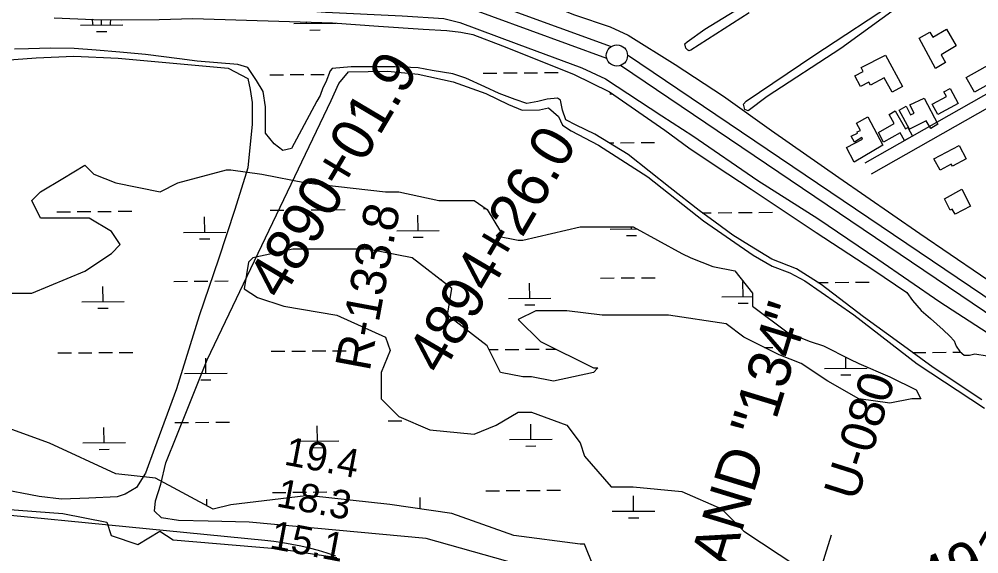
# Model space of a CAD drawing. Extents: x 3540316 to 3578335, y 553172 to 578787.
# Drawn here: x 3547262 to 3549520, y 567214 to 568472 of the extents above; entities that cross this region are included whole.
import ezdxf

# ---------------------------------------------------------------- set-up
doc = ezdxf.new("R2010")
doc.units = 0
for name, color, linetype in [('V-BLDG-OTLN', 7, 'Continuous'), ('V-CHAN-NAID', 7, 'Continuous'), ('V-LEVE-TOET', 7, 'Continuous'), ('V-RIVR-RANG', 7, 'Continuous'), ('V-RIVR-RANG-IDEN', 7, 'Continuous'), ('V-ROAD-CNTR', 7, 'Continuous'), ('V-SITE-VEGE', 7, 'Continuous'), ('V-SURV-IDEN', 7, 'Continuous'), ('V-SURV-LINE', 7, 'Continuous'), ('V-TOPO-MINR', 7, 'Continuous'), ('V-WETL-SWMP', 7, 'Continuous')]:
    doc.layers.add(name, color=color, linetype=linetype)

msp = doc.modelspace()

# ---------------------------------------------------------------- linework, layer by layer
at = {"layer": 'V-BLDG-OTLN'}
for points in [[(3549404.7, 568441.6), (3549411.5, 568430), (3549443.8, 568448.8), (3549467, 568409.1), (3549431, 568388.1), (3549441.6, 568370), (3549418.2, 568356.3), (3549379.8, 568427.7)], [(3549300.2, 568387.6), (3549340.4, 568313.5), (3549315.9, 568300.2), (3549297.5, 568334.2), (3549265, 568316.6), (3549260.9, 568324.2), (3549242, 568314), (3549228.6, 568338.9), (3549247.8, 568349.2), (3549242.9, 568358.2)], [(3549554.8, 568370.9), (3549574.4, 568336.3), (3549510, 568300), (3549490.2, 568335)], [(3549410.6, 568272.1), (3549411.9, 568273), (3549443.7, 568290), (3549437.7, 568301.3), (3549452.5, 568309.2), (3549471.6, 568273.4), (3549423.5, 568247.8)], [(3549357.9, 568270.4), (3549391.5, 568286.6), (3549423.9, 568225.2), (3549407, 568214.8), (3549396, 568233.2), (3549357.2, 568213.5), (3549332.3, 568258.1), (3549349.4, 568267.2), (3549359.5, 568246.8), (3549368.2, 568251)], [(3549283.8, 568205.2), (3549321, 568226.6), (3549308.9, 568247.8), (3549323.4, 568256.1), (3549347.5, 568214.1), (3549352.6, 568217), (3549364.1, 568197.1), (3549345.3, 568186.3), (3549335, 568204.3), (3549295.9, 568182.8)], [(3549259.2, 568242), (3549294.4, 568175.6), (3549227.1, 568135.8), (3549209, 568170.1), (3549246.5, 568189.8), (3549244.6, 568193.4), (3549227.8, 568182.7), (3549220, 568196.6), (3549234.9, 568203.8), (3549233.6, 568206.7), (3549241.4, 568210.1), (3549232, 568227.2)], [(3549429.4, 568116.9), (3549414.3, 568143.4), (3549473.4, 568175.1), (3549490.2, 568143.7), (3549457.7, 568126.3), (3549455.3, 568130.8)], [(3549479.9, 568071.7), (3549500.5, 568032), (3549464, 568013), (3549457.6, 568025.3), (3549452.8, 568022.8), (3549439.1, 568049.1)]]:
    msp.add_lwpolyline(points, close=True, dxfattribs=at)
at = {"layer": 'V-LEVE-TOET'}
for points in [[(3547740.4, 568609.2), (3547885.3, 568608.2), (3548075.1, 568600.8), (3548243, 568593), (3548285, 568586), (3548432, 568537), (3548569, 568482.3), (3548652.6, 568454.3), (3548695, 568434.6), (3548805.3, 568365.5), (3548919, 568290.6), (3549032.2, 568209.9), (3549190.9, 568099.3), (3549381.1, 567967.7), (3549524, 567870.8), (3549685.8, 567762.2), (3549864, 567644.5), (3550011.8, 567540.4), (3550143.1, 567453.9), (3550243.6, 567377.8)], [(3547729.2, 568503.5), (3547828.5, 568500.7), (3547982.8, 568488.8), (3548163.5, 568480.2), (3548261.1, 568473.6), (3548299, 568464.6), (3548431.9, 568415.2), (3548585.9, 568358), (3548641.4, 568332.1), (3548774, 568244.8), (3548846.9, 568197.5), (3549000.4, 568092.2), (3549141.2, 568002.9), (3549282.4, 567907.4), (3549428.5, 567807), (3549582.3, 567707.3), (3549721.7, 567617.3), (3549855.6, 567525.7), (3550026.9, 567407.2), (3550093.6, 567363.1)]]:
    msp.add_lwpolyline(points, dxfattribs=at)
at = {"layer": 'V-RIVR-RANG'}
msp.add_line((3549172.9, 567257.8), (3548625.9, 565522), dxfattribs=at)
at = {"layer": 'V-ROAD-CNTR'}
for points in [[(3549252.6, 568134.4), (3549839.8, 568467.5)], [(3549267.4, 568108.3), (3549854.6, 568441.4)]]:
    msp.add_lwpolyline(points, dxfattribs=at)
at = {"layer": 'V-SITE-VEGE'}
for p, q in [((3547229, 568376), (3547302.2, 568381.2)), ((3547302.2, 568381.2), (3547390.7, 568384.9)), ((3547390.7, 568384.9), (3547495.6, 568380.3)), ((3547495.6, 568380.3), (3547753.8, 568357)), ((3547753.8, 568357), (3547800.6, 568332.6)), ((3547800.6, 568332.6), (3547805.7, 568306.9)), ((3547805.7, 568306.9), (3547810.8, 568276.1)), ((3547810.8, 568276.1), (3547810.8, 568224.7)), ((3547810.8, 568224.7), (3547800.5, 568121.9)), ((3547800.5, 568121.9), (3547769.7, 568024.3)), ((3547769.7, 568024.3), (3547731.7, 567907.5)), ((3547731.7, 567907.5), (3547685.8, 567773.9)), ((3547685.8, 567773.9), (3547632.9, 567602)), ((3547632.9, 567602), (3547581.1, 567461.5)), ((3547581.1, 567461.5), (3547559.2, 567403.5)), ((3547559.2, 567403.5), (3547538.3, 567370.2)), ((3547309.7, 567348.9), (3547197.9, 567369.6)), ((3547511.7, 567354.5), (3547492.9, 567348.1)), ((3547538.3, 567370.2), (3547511.7, 567354.5)), ((3547361.7, 567342.6), (3547309.7, 567348.9)), ((3547426.5, 567344.9), (3547361.7, 567342.6)), ((3547492.9, 567348.1), (3547426.5, 567344.9))]:
    msp.add_line(p, q, dxfattribs=at)
for points in [[(3548979.5, 568487.3), (3548842.3, 568399.3), (3548837.8, 568398), (3548835.2, 568399.3), (3548830.6, 568403.8), (3548828.7, 568414.2), (3548833.9, 568418.7), (3548875.3, 568448.5), (3549002.8, 568526.8)], [(3549341.3, 568509.4), (3549195.7, 568403.2), (3549022.2, 568289.9), (3548977.6, 568256.3), (3548969.8, 568259.5), (3548966.6, 568271.8), (3548973, 568278.9), (3549131.6, 568387), (3549334.8, 568521)], [(3549150, 566988.1), (3548219.5, 567249.8), (3547803.5, 567288.5), (3547707.2, 567290.4), (3547637.5, 567292), (3547597.3, 567298.2), (3547580.7, 567314.1), (3547582.9, 567338.6), (3547596, 567377.8), (3547607.1, 567427.9), (3547658.8, 567556.6), (3547704.6, 567670.5), (3547996.2, 568280.9), (3548014.4, 568320.5), (3548037.4, 568348.5), (3548129.6, 568350.1), (3548201.2, 568342.7), (3548283.5, 568324.6), (3548360.1, 568297.5), (3548413.6, 568271.1), (3548445.7, 568258), (3548486.1, 568258.8), (3548507.5, 568263.7), (3548531.4, 568243.2), (3548540.4, 568222.6), (3548561, 568209.4), (3548625.2, 568175.7), (3548741.3, 568100.8), (3548872.2, 567997.9), (3548989.1, 567916.4), (3549033.6, 567890.9), (3549075.6, 567875.3), (3549111, 567856.3), (3549226.2, 567776.5), (3549375.3, 567661.3), (3549533.3, 567556.7)]]:
    msp.add_lwpolyline(points, dxfattribs=at)
at = {"layer": 'V-SURV-LINE'}
for points in [[(3548294.1, 568539.3), (3548654.9, 568407.6)], [(3548644.6, 568379.4), (3548283.8, 568511.1)], [(3548693.5, 568387.9), (3550036.7, 567480.5)], [(3550019.9, 567455.6), (3548676.7, 568363.1)]]:
    msp.add_lwpolyline(points, dxfattribs=at)
msp.add_circle((3548668.6, 568386.7), 25, dxfattribs=at)
at = {"layer": 'V-TOPO-MINR'}
msp.add_lwpolyline([(3548007.1, 567208.3), (3547986.8, 567215.2), (3547966.4, 567221.5), (3547945.6, 567227), (3547924.7, 567231.9), (3547903.7, 567235.9), (3547882.5, 567239.5), (3547861.3, 567242.5), (3547840, 567244.9), (3546866.5, 567340.8), (3546827.9, 567343.8), (3546789.2, 567345.7), (3546750.5, 567345.8), (3546711.8, 567344.9), (3546673.1, 567342.9), (3546634.4, 567340.7), (3546607.3, 567338.8)], dxfattribs=at)
at = {"layer": 'V-WETL-SWMP'}
for p, q in [((3547406.3, 568457.9), (3547506.3, 568458.7)), ((3547456.3, 568458.3), (3547456.2, 568471.5)), ((3547908.2, 568461.8), (3548008.2, 568462.6)), ((3547958.2, 568462.2), (3547958.1, 568465)), ((3547444.4, 568442.8), (3547468.4, 568443)), ((3547946.3, 568446.6), (3547970.3, 568446.8)), ((3548354.1, 568345.1), (3548386.1, 568345.4)), ((3548402.1, 568345.5), (3548434.1, 568345.8)), ((3548450.1, 568345.9), (3548482.1, 568346.1)), ((3548498.1, 568346.3), (3548530.1, 568346.5)), ((3547852.2, 568341.3), (3547884.2, 568341.5)), ((3547900.2, 568341.6), (3547932.2, 568341.9)), ((3547948.2, 568342), (3547980.2, 568342.3)), ((3548651.8, 568296.7), (3548657, 568296.7)), ((3548650.2, 568181.2), (3548661.3, 568181.3)), ((3548677.3, 568181.5), (3548709.3, 568181.7)), ((3548725.3, 568181.8), (3548757.3, 568182.1)), ((3547365, 568097), (3547417, 568128.2)), ((3547417, 568128.2), (3547437.8, 568107.4)), ((3547312.9, 568065.9), (3547365, 568097)), ((3547437.8, 568107.4), (3547489.8, 568086.7)), ((3547635.5, 568086.7), (3547749.9, 568117.9)), ((3547749.9, 568117.9), (3547760.3, 568117.9)), ((3547760.3, 568117.9), (3547833.1, 568107.5)), ((3547833.1, 568107.5), (3547937.2, 568086.8)), ((3547489.8, 568086.7), (3547593.8, 568066)), ((3547593.8, 568066), (3547635.5, 568086.7)), ((3547937.2, 568086.8), (3548124.4, 568066.1)), ((3547292.1, 568045.2), (3547312.9, 568065.9)), ((3548124.4, 568066.1), (3548134.8, 568066.1)), ((3548134.8, 568066.1), (3548155.6, 568066.1)), ((3548155.6, 568066.1), (3548249.3, 568045.3)), ((3547312.9, 568003.7), (3547292.1, 568045.2)), ((3548249.3, 568045.3), (3548332.5, 568045.3)), ((3548332.5, 568045.3), (3548363.7, 568024.6)), ((3547351.2, 568018.8), (3547383.2, 568019)), ((3547399.2, 568019.2), (3547431.2, 568019.4)), ((3547447.2, 568019.5), (3547479.2, 568019.8)), ((3547495.2, 568019.9), (3547527.2, 568020.2)), ((3547698.9, 567970.8), (3547698.7, 568006.8)), ((3547853.1, 568022.7), (3547885.1, 568022.9)), ((3547901.1, 568023), (3547933.1, 568023.3)), ((3547949.1, 568023.4), (3547981.1, 568023.7)), ((3547997.1, 568023.8), (3548029.1, 568024)), ((3548200.8, 567974.7), (3548200.5, 568010.6)), ((3548355, 568026.5), (3548360.7, 568026.6)), ((3548363.7, 568024.6), (3548394.9, 567972.7)), ((3548869.3, 568016.4), (3548890.6, 568016.6)), ((3548906.6, 568016.7), (3548938.6, 568017)), ((3548954.6, 568017.1), (3548986.6, 568017.3)), ((3549002.6, 568017.5), (3549034.6, 568017.7)), ((3547375.3, 568003.7), (3547312.9, 568003.7)), ((3547427.4, 568003.7), (3547375.3, 568003.7)), ((3547479.4, 567972.6), (3547427.4, 568003.7)), ((3547500.2, 567941.5), (3547479.4, 567972.6)), ((3547648.9, 567970.4), (3547748.9, 567971.2)), ((3548150.8, 567974.3), (3548250.8, 567975.1)), ((3548394.9, 567972.7), (3548384.5, 567962.4)), ((3548384.5, 567962.4), (3548436.5, 567952)), ((3548446.9, 567952), (3548582.2, 567983.1)), ((3548582.2, 567983.1), (3548655, 567983.2)), ((3548652.7, 567978.2), (3548715.3, 567978.6)), ((3548655, 567983.2), (3548707, 567983.2)), ((3548690.8, 567963), (3548714.8, 567963.2)), ((3548702.7, 567978.5), (3548702.7, 567983.2)), ((3548707, 567983.2), (3548821.4, 567920.9)), ((3547479.4, 567920.7), (3547500.2, 567941.5)), ((3547687, 567955.3), (3547711, 567955.5)), ((3548188.9, 567959.2), (3548212.9, 567959.4)), ((3548436.5, 567952), (3548446.9, 567952)), ((3547416.9, 567879.2), (3547479.4, 567920.7)), ((3547905.9, 567931.2), (3547812.3, 567910.4)), ((3547999.6, 567931.2), (3547905.9, 567931.2)), ((3548082.8, 567931.2), (3547999.6, 567931.2)), ((3548186.8, 567910.5), (3548082.8, 567931.2)), ((3548821.4, 567920.9), (3548842.2, 567910.6)), ((3547801.9, 567900), (3547791.5, 567837.8)), ((3547812.3, 567910.4), (3547801.9, 567900)), ((3548280.4, 567837.9), (3548186.8, 567910.5)), ((3548842.2, 567910.6), (3548894.3, 567889.8)), ((3547292.1, 567827.3), (3547416.9, 567879.2)), ((3548894.3, 567889.8), (3548946.3, 567879.5)), ((3548946.3, 567879.5), (3548987.9, 567827.6)), ((3547626.4, 567855), (3547658.4, 567855.2)), ((3547674.4, 567855.4), (3547706.4, 567855.6)), ((3547722.4, 567855.7), (3547754.4, 567856)), ((3548252.1, 567859.8), (3548256.3, 567859.8)), ((3548463.5, 567815.1), (3548463.2, 567851)), ((3548630.2, 567862.7), (3548662.2, 567863)), ((3548678.2, 567863.1), (3548710.2, 567863.3)), ((3548726.2, 567863.5), (3548758.2, 567863.7)), ((3548965.4, 567818.9), (3548965.1, 567854.9)), ((3549141.5, 567852.4), (3549165.8, 567852.5)), ((3549181.8, 567852.7), (3549213.8, 567852.9)), ((3549229.8, 567853), (3549261.8, 567853.3)), ((3547156.8, 567827.3), (3547292.1, 567827.3)), ((3547459.7, 567807.3), (3547459.4, 567843.3)), ((3547791.5, 567837.8), (3547822.7, 567817)), ((3548270, 567775.6), (3548280.4, 567837.9)), ((3548987.9, 567827.6), (3548987.9, 567796.5)), ((3547409.7, 567806.9), (3547509.7, 567807.7)), ((3547822.7, 567817), (3547885.1, 567796.3)), ((3548413.5, 567814.7), (3548513.5, 567815.5)), ((3548915.4, 567818.6), (3548987.9, 567819.1)), ((3548953.5, 567803.4), (3548977.5, 567803.6)), ((3547447.8, 567791.8), (3547471.8, 567792)), ((3547885.1, 567796.3), (3548009.9, 567775.6)), ((3548478.1, 567786), (3548436.5, 567765.3)), ((3548451.6, 567799.6), (3548475.6, 567799.8)), ((3548550.9, 567786), (3548478.1, 567786)), ((3548634.1, 567775.7), (3548550.9, 567786)), ((3548987.9, 567796.5), (3549071.1, 567734.3)), ((3548009.9, 567775.6), (3548124.4, 567723.7)), ((3548363.6, 567703), (3548270, 567775.6)), ((3548436.5, 567765.3), (3548488.5, 567713.4)), ((3548769.4, 567775.7), (3548634.1, 567775.7)), ((3548790.2, 567775.7), (3548769.4, 567775.7)), ((3548925.4, 567755), (3548790.2, 567775.7)), ((3548967.1, 567723.9), (3548925.4, 567755)), ((3548124.4, 567723.7), (3548134.8, 567692.6)), ((3548488.5, 567713.4), (3548613.3, 567651.2)), ((3549050.3, 567682.4), (3548967.1, 567723.9)), ((3549071.1, 567734.3), (3549123.1, 567713.5)), ((3549123.1, 567713.5), (3549154.3, 567703.1)), ((3547855.6, 567690.5), (3547887.6, 567690.7)), ((3547903.6, 567690.8), (3547935.6, 567691.1)), ((3547951.6, 567691.2), (3547983.6, 567691.5)), ((3547999.6, 567691.6), (3548031.6, 567691.8)), ((3548134.8, 567692.6), (3548113.9, 567640.7)), ((3548394.8, 567640.8), (3548363.6, 567703)), ((3548367.9, 567694.4), (3548389.5, 567694.6)), ((3548405.5, 567694.7), (3548437.5, 567695)), ((3548453.5, 567695.1), (3548485.5, 567695.3)), ((3548501.5, 567695.5), (3548524.1, 567695.6)), ((3549016.1, 567699.4), (3549035.4, 567699.6)), ((3549154.3, 567703.1), (3549216.7, 567672)), ((3547353.7, 567686.6), (3547385.7, 567686.9)), ((3547401.7, 567687), (3547433.7, 567687.2)), ((3547449.7, 567687.3), (3547481.7, 567687.6)), ((3547497.7, 567687.7), (3547529.7, 567688)), ((3547701.4, 567638.6), (3547701.2, 567674.6)), ((3549102.3, 567661.6), (3549050.3, 567682.4)), ((3549207.1, 567650.2), (3549206.9, 567676.9)), ((3549216.7, 567672), (3549237.5, 567661.7)), ((3549364.2, 567687.6), (3549395, 567687.8)), ((3549411, 567687.9), (3549443, 567688.2)), ((3549459, 567688.3), (3549477.2, 567688.4)), ((3548613.3, 567651.2), (3548623.7, 567651.2)), ((3548623.7, 567651.2), (3548613.3, 567640.8)), ((3549164.7, 567620.2), (3549102.3, 567661.6)), ((3549157.1, 567649.8), (3549257.1, 567650.6)), ((3549237.5, 567661.7), (3549310.4, 567630.6)), ((3547651.4, 567638.2), (3547751.4, 567639)), ((3547689.6, 567623.1), (3547713.6, 567623.3)), ((3548113.9, 567640.7), (3548113.9, 567578.5)), ((3548446.9, 567630.4), (3548394.8, 567640.8)), ((3548467.7, 567630.4), (3548446.9, 567630.4)), ((3548519.7, 567620), (3548467.7, 567630.4)), ((3548613.3, 567640.8), (3548519.7, 567620)), ((3549195.2, 567634.7), (3549219.2, 567634.9)), ((3549310.4, 567630.6), (3549372.8, 567599.4)), ((3549237.5, 567578.7), (3549164.7, 567620.2)), ((3548113.9, 567578.5), (3548155.5, 567537)), ((3549310.3, 567568.3), (3549237.5, 567578.7)), ((3549362.4, 567578.7), (3549310.3, 567568.3)), ((3549383.2, 567578.7), (3549362.4, 567578.7)), ((3549372.8, 567599.4), (3549383.2, 567578.7)), ((3548155.5, 567537), (3548228.4, 567505.9)), ((3548384.4, 567516.3), (3548436.4, 567547.4)), ((3548436.4, 567547.4), (3548467.6, 567547.4)), ((3548467.6, 567547.4), (3548550.9, 567516.3)), ((3547333.6, 567474.6), (3547219.2, 567516.1)), ((3547462.2, 567475.1), (3547461.9, 567511.1)), ((3547628.9, 567522.8), (3547660.9, 567523)), ((3547676.9, 567523.2), (3547708.9, 567523.4)), ((3547724.9, 567523.5), (3547756.9, 567523.8)), ((3547964.1, 567479), (3547963.8, 567515)), ((3548130.8, 567526.7), (3548162.8, 567526.9)), ((3548178.8, 567527), (3548178.8, 567527)), ((3548332.4, 567495.5), (3548384.4, 567516.3)), ((3548466, 567482.9), (3548465.7, 567518.8)), ((3548550.9, 567516.3), (3548582.1, 567474.8)), ((3548228.4, 567505.9), (3548332.4, 567495.5)), ((3547489.7, 567402), (3547333.6, 567474.6)), ((3547412.2, 567474.8), (3547512.2, 567475.5)), ((3547914.1, 567478.6), (3548014.1, 567479.4)), ((3548416, 567482.5), (3548516, 567483.3)), ((3548454.1, 567467.4), (3548478.1, 567467.6)), ((3548582.1, 567474.8), (3548592.5, 567443.7)), ((3547450.3, 567459.6), (3547474.3, 567459.8)), ((3547952.2, 567463.5), (3547976.2, 567463.7)), ((3548592.5, 567443.7), (3548654.9, 567371.1)), ((3547583.3, 567391.6), (3547489.7, 567402)), ((3547718.5, 567319), (3547583.3, 567391.6)), ((3547858.1, 567358.3), (3547890.1, 567358.5)), ((3547906.1, 567358.7), (3547938.1, 567358.9)), ((3547954.1, 567359), (3547986.1, 567359.3)), ((3548002.1, 567359.4), (3548034.1, 567359.6)), ((3548360, 567362.2), (3548392, 567362.4)), ((3548408, 567362.5), (3548440, 567362.8)), ((3548456, 567362.9), (3548488, 567363.1)), ((3548504, 567363.3), (3548536, 567363.5)), ((3548654.9, 567371.1), (3548706.9, 567371.1)), ((3548706.9, 567371.1), (3548821.3, 567360.7)), ((3548821.3, 567360.7), (3548915, 567319.3)), ((3547703.8, 567327), (3547703.7, 567342.4)), ((3547760.2, 567329.4), (3547718.5, 567319)), ((3547937, 567350.2), (3547760.2, 567329.4)), ((3547947.4, 567350.2), (3547937, 567350.2)), ((3548134.7, 567329.5), (3547947.4, 567350.2)), ((3548280.3, 567308.8), (3548134.7, 567329.5)), ((3548205.8, 567319.4), (3548205.6, 567346.2)), ((3548707.7, 567314.2), (3548707.5, 567350.1)), ((3547229.6, 567319), (3547364.8, 567308.6)), ((3547364.8, 567308.6), (3547468.8, 567287.9)), ((3548426, 567256.9), (3548280.3, 567308.8)), ((3548657.7, 567313.8), (3548757.7, 567314.5)), ((3548915, 567319.3), (3548967, 567267.4)), ((3547468.8, 567287.9), (3547479.2, 567256.8)), ((3548695.8, 567298.7), (3548719.8, 567298.8)), ((3547541.7, 567236), (3547593.7, 567267.1)), ((3547593.7, 567267.1), (3547624.9, 567246.4)), ((3548967, 567267.4), (3549091.8, 567184.4)), ((3547479.2, 567256.8), (3547541.7, 567236)), ((3547624.9, 567246.4), (3547874.6, 567225.7)), ((3548582, 567236.2), (3548426, 567256.9)), ((3547874.6, 567225.7), (3548009.8, 567205)), ((3548592.4, 567236.2), (3548582, 567236.2)), ((3548613.2, 567184.3), (3548592.4, 567236.2))]:
    msp.add_line(p, q, dxfattribs=at)
for points in [[(3547344.9, 568475.6), (3547437.2, 568471.8), (3547502.9, 568470.8), (3547591.8, 568471.1), (3547671.1, 568473.5), (3547999.6, 568463.8), (3548108, 568456.1), (3548212.5, 568448.6), (3548268.2, 568445.4), (3548301.5, 568441.5), (3548329.3, 568436.4), (3548399.5, 568409.2), (3548566.2, 568342.6), (3548651, 568300.8), (3548781.7, 568210.9), (3548837.7, 568169.2), (3548901.8, 568126.5), (3548984.3, 568071.8), (3549137.1, 567970.2), (3549270.7, 567883.2), (3549350.7, 567829.2), (3549363.6, 567809.7), (3549384, 567786.8), (3549406.3, 567768), (3549436.4, 567741.2), (3549452, 567725.9), (3549462.3, 567715.3), (3549466.5, 567702.3), (3549475.3, 567690), (3549485.6, 567681.6), (3549497.9, 567681.3), (3549510.9, 567684.5), (3549539.7, 567680)], [(3547962.4, 568278.9), (3547903.3, 568168.1), (3547882.7, 568163), (3547862.2, 568178.4), (3547841.6, 568204.1), (3547841.6, 568235), (3547841.7, 568265.8), (3547836.5, 568301.8), (3547821.1, 568327.5), (3547800.6, 568358.3), (3547776.8, 568365.4), (3547681.5, 568373.2), (3547639.2, 568378.5), (3547559.9, 568389.2), (3547499.1, 568394.9), (3547443.7, 568399.3), (3547391.7, 568402.9), (3547336.3, 568403.9), (3547284.3, 568402), (3547251.5, 568401.5)], [(3549334.2, 567709.7), (3549248.4, 567771.9), (3549149.1, 567847.6), (3549091.1, 567884.4), (3549033.2, 567907.7), (3548980.8, 567939.1), (3548941, 567963.7), (3548899.6, 567994.1), (3548862.3, 568021.6), (3548793.7, 568075.3), (3548695.3, 568153.9), (3548616.7, 568201.5), (3548572.4, 568222.8), (3548548.4, 568235.1), (3548540.7, 568258.1), (3548535.5, 568281.4), (3548529, 568286.3), (3548504.7, 568284.3), (3548482.7, 568278.5), (3548456.5, 568273.9), (3548429.3, 568283.3), (3548391.8, 568297.6), (3548357.5, 568313.1), (3548313.2, 568333.5), (3548282.7, 568343.5), (3548233.9, 568351.6), (3548201.2, 568358), (3548145.9, 568360.3), (3548043.6, 568360.3), (3547998.6, 568355.7), (3547994.1, 568350.6), (3547983.7, 568324), (3547976.5, 568310.3), (3547970.3, 568292.2), (3547962.4, 568278.9)], [(3549527.1, 567576.5), (3549412.2, 567652.2), (3549334.2, 567709.7)]]:
    msp.add_lwpolyline(points, dxfattribs=at)
for centre, start, end in [((3547401, 568458.3), 359.6699, 22.7217), ((3547511.5, 568459.2), 160.1056, 181.2135), ((3547902.9, 568462.2), 359.6699, 5.5662), ((3548013.4, 568463.1), 177.7468, 181.2135)]:
    msp.add_arc(centre, 35.2, start, end, dxfattribs=at)

# ---------------------------------------------------------------- texts
at = {"layer": 'V-CHAN-NAID'}
msp.add_text('WOODLAND "134" ', height=100, rotation=72.9671, dxfattribs=at).set_placement((3548787.6, 566693.2))
at = {"layer": 'V-RIVR-RANG'}
for s, p in [('19.4', (3547883.4, 567424.1)), ('18.3', (3547865.1, 567325.7)), ('15.1', (3547849.1, 567227))]:
    msp.add_text(s, height=67, rotation=349.3083, dxfattribs=at).set_placement(p)
at = {"layer": 'V-RIVR-RANG-IDEN'}
for s, rotation, p in [('R-133.8', 79.4452, (3548086.7, 567641.3)), ('U-080', 72.3673, (3549232.9, 567335.7))]:
    msp.add_text(s, height=83, rotation=rotation, dxfattribs=at).set_placement(p)
at = {"layer": 'V-SURV-IDEN'}
for s, rotation, p in [('4890+01.9', 59.3114, (3547880, 567808.2)), ('4894+26.0', 59.6155, (3548255.5, 567631.7)), ('4910+87.1', 23.5279, (3549405.6, 567100.8))]:
    msp.add_text(s, height=100, rotation=rotation, dxfattribs=at).set_placement(p)

doc.saveas('drawing.dxf')
